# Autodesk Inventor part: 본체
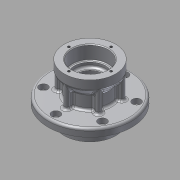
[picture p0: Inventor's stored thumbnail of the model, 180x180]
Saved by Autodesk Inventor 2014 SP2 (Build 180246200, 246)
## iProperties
Created: 2024-04
Part Number: 본체
Material: 알루미늄 6061
Document SubType Name: Modeling
Designer: Administrator
Density: 2.71 g/cm^3
Appearance: 알루미늄 - 평지
Mass: 492.731 g
Surface Area: 448.775 cm^2
Volume: 181.819 cm^3
Author: Administrator
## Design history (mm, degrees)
sketch "스케치1"
  geometry: C1 r 54.5 at (0, 0); 1 further point
  constraints: 1 centre point, 1 coincident
  dimensions: "d0" = 109 diameter of C1
extrude "돌출1" new body sketch "스케치1" stored distance "d1" = 10; taper "d2" = 0 deg
sketch "스케치2"
  geometry: L1 (0, 78.971)-(0, -83.353); L2 (54.5, 5)-(-54.5, 5) reference; L3 (-54.5, -5)-(54.5, -5) reference; L4 (0, 5)-(25.5, 5); L5 (25.5, 5)-(25.5, 33); L6 (25.5, 33)-(0, 33); L7 (0, 33)-(0, 5); L8 (0, 33)-(33.5, 33); L9 (33.5, 33)-(33.5, 45); L10 (33.5, 45)-(0, 45); L11 (0, 45)-(0, 33); L12 (0, -5)-(38.5, -5); L13 (38.5, -5)-(38.5, -10); L14 (38.5, -10)-(0, -10); L15 (0, -10)-(0, -5); L16 (0, -10)-(33.5, -10); L17 (33.5, -10)-(33.5, -25); L18 (33.5, -25)-(0, -25); L19 (0, -25)-(0, -10); L20 (33.5, 33)-(25.5, 23.121); 1 further point
  constraints: 36 end point, 8 parallel, 4 horizontal, 4 perpendicular, 2 midpoint, 2 point on line, 1 vertical
  dimensions: "d3" = 51 diameter of L5 L1; "d4" = 67 diameter of L9 L1; "d5" = 67 diameter of L17 L1; "d6" = 77 diameter of L13 L1; "d7" = 5 distance between parallel lines of L12 L16; "d8" = 20 distance between parallel lines of L3 L18; "d9" = 12 distance between parallel lines of L10 L6; "d10" = 70 distance between parallel lines of L18 L10; "d14" = 39 deg angle of L9 L20
revolve "회전1" sketch "스케치2" stored, may be unused: angle "d11" = 90 deg
sketch "스케치3"
  geometry: L1 (0, -76.3)-(0, 76.3) reference; L2 (-14.095, 33.5)-(15.539, 33.5); L3 (-3, 25.323)-(-3, 30.5); L4 (3, 25.323)-(3, 30.5); A1 r 25.5 centre (0, 0) between (-3, 25.323) and (3, 25.323) reference; A2 r 3 centre (0, 30.5) between (3, 30.5) and (-3, 30.5)
  constraints: 6 end point, 4 point on circle, 2 perpendicular, 2 tangent, 1 centre point, 1 parallel, 1 other
  dimensions: "d15" = 6 diameter of A2; "d16" = 6 distance between parallel lines of L4 L3; "d17" = 33.5 distance from line of A1.centre L2
extrude "돌출2" join sketch "스케치3" distance "d18" = 28; taper "d19" = 0 deg
sketch "스케치4"
  geometry: L1 (0, 75.538)-(0, -89.558); L2 (-33.5, 45)-(33.5, 45) reference; L3 (-33.5, -25)-(33.5, -25) reference; L4 (0, 45)-(23.5, 45); L5 (23.5, 45)-(23.5, 27); L6 (23.5, 27)-(0, 27); L7 (0, 27)-(0, 45); L8 (0, 27)-(20.5, 27); L9 (20.5, 27)-(20.5, 21); L10 (20.5, 21)-(0, 21); L11 (0, 21)-(0, 27); L12 (0, 21)-(16, 21); L13 (16, 21)-(16, -1); L14 (16, -1)-(0, -1); L15 (0, -1)-(0, 21); L16 (0, -1)-(20.5, -1); L17 (20.5, -1)-(20.5, -7); L18 (20.5, -7)-(0, -7); L19 (0, -7)-(0, -1); L20 (0, -7)-(23.5, -7); L21 (23.5, -7)-(23.5, -25); L22 (23.5, -25)-(0, -25); L23 (0, -25)-(0, -7); 1 further point
  constraints: 42 end point, 10 parallel, 5 horizontal, 5 perpendicular, 2 point on line, 1 midpoint, 1 vertical
  dimensions: "d23" = 47 diameter of L5 L1; "d24" = 41 diameter of L9 L1; "d25" = 32 diameter of L13 L1; "d26" = 41 diameter of L17 L1; "d27" = 47 diameter of L21 L1; "d28" = 18 distance between parallel lines of L2 L6; "d29" = 6 distance between parallel lines of L6 L12; "d30" = 6 distance between parallel lines of L18 L14; "d31" = 18 distance between parallel lines of L3 L18
revolve "회전2" sketch "스케치4" stored, may be unused: angle "d32" = 90 deg
sketch "스케치5"
  geometry: L1 (0, -76.3)-(0, 76.3) reference; C1 r 23.5 at (0, 0) reference; 1 further point
  constraints: 1 point on line
  dimensions: "d33" = 27.5 distance of C1.centre point (0, 27.5)
hole "구멍1" sketch "스케치5" at (0, 27.5) diameter "d34" = 3.242; stored, may be unused: countersink angle "d38" = 90 deg, drill point angle "d40" = 118 deg; dims "d35" = 8, "d36" = 4, "d37" = 2, "d39" = 10
sketch "스케치6"
  geometry: L1 (0, -76.3)-(0, 76.3) reference; C1 r 23.5 at (0, 0) reference; 1 further point
  constraints: 1 point on line
  dimensions: "d44" = 27.5 distance of C1.centre point (0, 27.5)
hole "구멍2" sketch "스케치6" at (0, 27.5) diameter "d45" = 3.242; stored, may be unused: countersink angle "d49" = 90 deg, drill point angle "d51" = 118 deg; dims "d46" = 8, "d47" = 4, "d48" = 2, "d50" = 10
sketch "스케치7"
  geometry: L1 (0, -76.3)-(0, 76.3) reference; A1 r 25.5 centre (0, 0) between (-3, 25.323) and (-20.43, 15.26) reference; 1 further point
  constraints: 1 point on line
  dimensions: "d55" = 44.5 distance of A1.centre point (0, 44.5)
hole "구멍3" sketch "스케치7" at (0, 44.5) diameter "d56" = 6.6; stored, may be unused: countersink angle "d60" = 90 deg, drill point angle "d62" = 0 deg; dims "d57" = 8, "d58" = 11, "d59" = 6.6, "d61" = 10
node "작업 평면1"
fillet "모깎기1" dims "d71" = 1
fillet "모깎기2" dims "d72" = 3
fillet "모깎기3" dims "d73" = 3
chamfer "모따기1" distance "d76" = 1; stored, may be unused: second distance "d77" = 2, angle "d78" = 45 deg
fillet "모깎기6" dims "d79" = 3
chamfer "모따기2" distance "d80" = 1; stored, may be unused: second distance "d81" = 2, angle "d82" = 45 deg
chamfer "모따기4" distance "d86" = 1; stored, may be unused: second distance "d87" = 2, angle "d88" = 45 deg
chamfer "모따기5" distance "d89" = 1; stored, may be unused: second distance "d90" = 2, angle "d91" = 45 deg
fillet "모깎기7" dims "d95" = 3
fillet "모깎기8" dims "d96" = 3
chamfer "모따기7" distance "d97" = 1; stored, may be unused: second distance "d98" = 2, angle "d99" = 45 deg
node "작업 평면2"
sketch "스케치9"
  geometry: L1 (-33.5, 45)-(33.5, 45) reference; L2 (33.5, 45)-(33.5, 34) reference; 2 further points
  constraints: 1 other
  dimensions: "d101" = 6 distance from line of L1 point (0, 39); "d102" = 33.5 distance from line of L2 point (0, 39)
feature "엠보싱2" sketch "스케치9" dims "d2" = 0, "d3" = 51, "d4" = 67, "d5" = 67, "d6" = 77, "d7" = 5, "d8" = 20, "d9" = 12, "d10" = 70, "d14" = 39 deg, "d103" = 0.5, "d104" = 0
node "솔리드1"
pattern_circular "원형 패턴1" dims angle "d21" = 360 deg
pattern_circular "원형 패턴2" dims angle "d42" = 360 deg
pattern_circular "원형 패턴3" dims angle "d53" = 360 deg
pattern_circular "원형 패턴4" dims angle "d64" = 360 deg
other parameters: "d66" = 33.5, "d100" = 33.5
